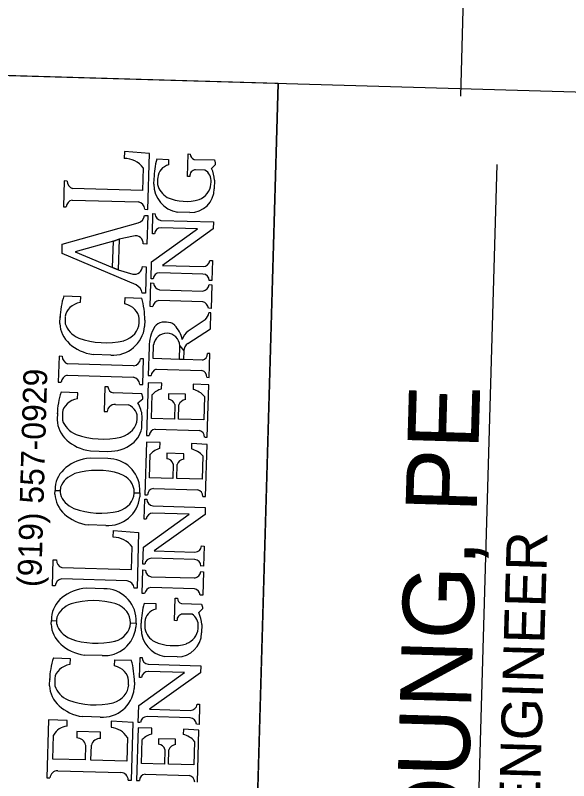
# Model space of a CAD drawing. Extents: x 2097846 to 2099709, y 989477 to 992073.
# Drawn here: x 2099288 to 2099390, y 991266.3 to 991407.2 of the extents above; entities that cross this region are included whole.
import ezdxf

# ---------------------------------------------------------------- set-up
doc = ezdxf.new("R2010")
doc.units = 0
for name, color, linetype in [('Exist Horizontal Alignment Tick Label', 7, 'Continuous'), ('Sheet Block Title CELL', 7, 'Continuous'), ('Sheet Data Field CELL', 7, 'Continuous'), ('Sheet Title CELL', 7, 'Continuous')]:
    doc.layers.add(name, color=color, linetype=linetype)

msp = doc.modelspace()

# ---------------------------------------------------------------- linework, layer by layer
at = {"layer": 'Sheet Block Title CELL'}
for p, q in [((2099308.13, 991382.15), (2099308.09, 991380.9)), ((2099312.76, 991381.78), (2099308.13, 991382.15)), ((2099312.46, 991371.51), (2099312.76, 991381.78)), ((2099319.73, 991377.59), (2099319.85, 991381.72)), ((2099319.85, 991381.72), (2099320.28, 991381.7)), ((2099314.09, 991380.79), (2099316.28, 991380.72)), ((2099316.28, 991380.72), (2099316.25, 991379.69)), ((2099321.01, 991380.72), (2099324.71, 991380.62)), ((2099324.85, 991379.74), (2099324.2, 991379.06)), ((2099324.71, 991380.62), (2099324.86, 991380.06)), ((2099324.86, 991380.06), (2099324.85, 991379.74)), ((2099311.58, 991379.13), (2099311.46, 991374.96)), ((2099322.95, 991378.75), (2099321.25, 991378.8)), ((2099313.55, 991376.13), (2099313.58, 991377.15)), ((2099320.16, 991377.57), (2099319.73, 991377.59)), ((2099324.75, 991376.89), (2099324.7, 991375.32)), ((2099297.01, 991376.74), (2099296.87, 991371.96)), ((2099297.59, 991376.72), (2099297.01, 991376.74)), ((2099324.07, 991376.14), (2099324.1, 991376.53)), ((2099311.46, 991374.96), (2099298.58, 991375.33)), ((2099298.52, 991373.23), (2099310.66, 991372.88)), ((2099296.87, 991371.96), (2099297.4, 991371.95)), ((2099311.91, 991371.53), (2099312.46, 991371.51)), ((2099311.85, 991370.4), (2099312.43, 991370.38)), ((2099312.43, 991370.38), (2099312.28, 991365.12)), ((2099313.28, 991367.02), (2099313.39, 991370.74)), ((2099313.39, 991370.74), (2099313.76, 991370.72)), ((2099320.2, 991370.93), (2099317.89, 991370.99)), ((2099296.68, 991365.13), (2099310.66, 991369.01)), ((2099314.87, 991369.48), (2099324.55, 991369.2)), ((2099324.55, 991369.2), (2099324.51, 991367.91)), ((2099313.14, 991361.87), (2099321.59, 991367.92)), ((2099313.66, 991367.01), (2099313.28, 991367.02)), ((2099321.59, 991367.92), (2099314.89, 991368.12)), ((2099324.51, 991367.91), (2099315.13, 991361.19)), ((2099306.09, 991365.67), (2099299.06, 991363.72)), ((2099305.94, 991360.79), (2099306.09, 991365.67)), ((2099307.14, 991366.01), (2099306.09, 991365.67)), ((2099306.09, 991365.67), (2099307.14, 991366.01)), ((2099307.14, 991366.01), (2099306.98, 991360.39)), ((2099309.81, 991366.56), (2099307.14, 991366.01)), ((2099296.63, 991363.41), (2099296.68, 991365.13)), ((2099312.28, 991365.12), (2099311.56, 991365.14)), ((2099310.27, 991357.6), (2099296.63, 991363.41)), ((2099299.06, 991363.72), (2099305.94, 991360.79)), ((2099313.05, 991358.73), (2099313.14, 991361.87)), ((2099323.86, 991362.1), (2099324.34, 991362.09)), ((2099324.34, 991362.09), (2099324.24, 991358.4)), ((2099305.94, 991360.79), (2099306.98, 991360.39)), ((2099306.98, 991360.39), (2099305.94, 991360.79)), ((2099306.98, 991360.39), (2099309.66, 991359.59)), ((2099311.47, 991360.97), (2099312.16, 991360.95)), ((2099312.16, 991360.95), (2099312.02, 991356.07)), ((2099315.13, 991361.19), (2099322.63, 991360.98)), ((2099313.42, 991358.72), (2099313.05, 991358.73)), ((2099322.59, 991359.6), (2099314.65, 991359.83)), ((2099312.9, 991353.61), (2099313.02, 991357.96)), ((2099313.02, 991357.96), (2099313.5, 991357.95)), ((2099323.74, 991357.65), (2099324.22, 991357.64)), ((2099324.24, 991358.4), (2099323.76, 991358.41)), ((2099324.22, 991357.64), (2099324.09, 991353.29)), ((2099312.02, 991356.07), (2099311.4, 991356.09)), ((2099314.58, 991356.71), (2099322.59, 991356.48)), ((2099296.96, 991355.59), (2099300.03, 991355.5)), ((2099300.03, 991355.5), (2099299.99, 991354.37)), ((2099308.22, 991354.13), (2099308.25, 991355.26)), ((2099308.25, 991355.26), (2099311.31, 991355.17)), ((2099322.56, 991354.51), (2099314.5, 991354.74)), ((2099313.38, 991353.59), (2099312.9, 991353.61)), ((2099324.09, 991353.29), (2099323.61, 991353.3)), ((2099296.24, 991350.47), (2099296.28, 991351.81)), ((2099324.07, 991352.48), (2099323.66, 991352.49)), ((2099323.98, 991349.53), (2099324.07, 991352.48)), ((2099310.82, 991350.64), (2099310.83, 991351.43)), ((2099311.88, 991351.13), (2099311.84, 991349.94)), ((2099322.99, 991351.19), (2099319.9, 991349.06)), ((2099319.82, 991346.82), (2099323.98, 991349.53)), ((2099312.68, 991346.2), (2099312.53, 991340.92)), ((2099313.44, 991344.03), (2099313.51, 991346.55)), ((2099318.26, 991343.89), (2099318.33, 991346.41)), ((2099318.33, 991346.41), (2099319.05, 991345.45)), ((2099318.33, 991346.41), (2099319.05, 991345.45)), ((2099296.08, 991344.47), (2099295.94, 991339.69)), ((2099296.66, 991344.45), (2099296.08, 991344.47)), ((2099305.6, 991344.69), (2099302.36, 991344.78)), ((2099319.05, 991345.45), (2099319, 991343.87)), ((2099323.85, 991344.95), (2099323.44, 991344.96)), ((2099323.72, 991340.58), (2099323.85, 991344.95)), ((2099309.79, 991342.71), (2099297.65, 991343.06)), ((2099311.67, 991343.97), (2099311.12, 991343.99)), ((2099311.53, 991339.24), (2099311.67, 991343.97)), ((2099318.26, 991343.89), (2099313.44, 991344.03)), ((2099319, 991343.87), (2099318.26, 991343.89)), ((2099319, 991343.87), (2099318.26, 991343.89)), ((2099322.53, 991343.77), (2099319, 991343.87)), ((2099313.96, 991342.09), (2099322.42, 991341.85)), ((2099297.59, 991340.96), (2099309.73, 991340.61)), ((2099312.53, 991340.92), (2099313.03, 991340.91)), ((2099323.32, 991340.59), (2099323.72, 991340.58)), ((2099295.94, 991339.69), (2099296.47, 991339.68)), ((2099304.5, 991338.82), (2099304.37, 991334.28)), ((2099305.11, 991338.81), (2099304.5, 991338.82)), ((2099310.98, 991339.26), (2099311.53, 991339.24)), ((2099312.49, 991339.58), (2099312.21, 991329.88)), ((2099315.02, 991339.51), (2099312.49, 991339.58)), ((2099314.99, 991338.44), (2099315.02, 991339.51)), ((2099320.82, 991339.35), (2099320.79, 991338.34)), ((2099323.68, 991339.18), (2099320.82, 991339.35)), ((2099323.41, 991329.56), (2099323.68, 991339.18)), ((2099299.51, 991337.76), (2099296.45, 991337.85)), ((2099299.48, 991336.63), (2099299.51, 991337.76)), ((2099311.31, 991337.57), (2099306.14, 991337.72)), ((2099311.53, 991336.96), (2099311.31, 991337.57)), ((2099313.09, 991333.03), (2099313.22, 991337.4)), ((2099316.26, 991337.57), (2099316.23, 991336.56)), ((2099319.4, 991337.48), (2099316.26, 991337.57)), ((2099319.37, 991336.48), (2099319.4, 991337.48)), ((2099310.61, 991335.87), (2099311.52, 991336.61)), ((2099311.52, 991336.61), (2099311.53, 991336.96)), ((2099322.87, 991337.08), (2099322.75, 991332.75)), ((2099306.49, 991335.61), (2099308.87, 991335.54)), ((2099317.42, 991335.57), (2099317.35, 991332.91)), ((2099318.1, 991332.89), (2099318.17, 991335.5)), ((2099295.77, 991334.07), (2099295.73, 991332.74)), ((2099304.37, 991334.28), (2099304.98, 991334.27)), ((2099311.35, 991331.6), (2099311.4, 991333.47)), ((2099317.35, 991332.91), (2099313.09, 991333.03)), ((2099322.75, 991332.75), (2099318.1, 991332.89)), ((2099313.79, 991331.04), (2099321.96, 991330.81)), ((2099312.21, 991329.88), (2099312.71, 991329.87)), ((2099322.92, 991329.58), (2099323.41, 991329.56)), ((2099312.18, 991328.63), (2099311.9, 991318.94)), ((2099314.71, 991328.56), (2099312.18, 991328.63)), ((2099314.68, 991327.49), (2099314.71, 991328.56)), ((2099320.51, 991328.41), (2099320.48, 991327.4)), ((2099323.37, 991328.23), (2099320.51, 991328.41)), ((2099323.09, 991318.62), (2099323.37, 991328.23)), ((2099301.85, 991327.05), (2099305.08, 991326.95)), ((2099312.78, 991322.09), (2099312.9, 991326.46)), ((2099315.95, 991326.62), (2099315.92, 991325.61)), ((2099319.09, 991326.53), (2099315.95, 991326.62)), ((2099319.06, 991325.53), (2099319.09, 991326.53)), ((2099322.56, 991326.13), (2099322.43, 991321.81)), ((2099305.05, 991325.62), (2099301.81, 991325.71)), ((2099317.11, 991324.63), (2099317.03, 991321.96)), ((2099317.78, 991321.94), (2099317.86, 991324.55)), ((2099317.03, 991321.96), (2099312.78, 991322.09)), ((2099322.43, 991321.81), (2099317.78, 991321.94)), ((2099295.33, 991319.1), (2099295.35, 991319.74)), ((2099295.37, 991320.39), (2099295.35, 991319.74)), ((2099295.35, 991319.74), (2099296.3, 991319.72)), ((2099295.35, 991319.74), (2099296.3, 991319.72)), ((2099309.92, 991319.35), (2099310.96, 991319.29)), ((2099309.92, 991319.35), (2099310.96, 991319.29)), ((2099309.92, 991319.27), (2099309.92, 991319.32)), ((2099310.96, 991319.29), (2099310.94, 991318.57)), ((2099310.96, 991319.29), (2099310.98, 991320.02)), ((2099313.48, 991320.1), (2099321.64, 991319.86)), ((2099311.77, 991314.46), (2099311.88, 991318.18)), ((2099311.88, 991318.18), (2099312.25, 991318.17)), ((2099311.9, 991318.94), (2099312.39, 991318.93)), ((2099322.6, 991318.63), (2099323.09, 991318.62)), ((2099313.36, 991316.92), (2099323.03, 991316.65)), ((2099323.03, 991316.65), (2099323, 991315.35)), ((2099311.62, 991309.31), (2099320.07, 991315.37)), ((2099320.07, 991315.37), (2099313.37, 991315.56)), ((2099323, 991315.35), (2099313.62, 991308.63)), ((2099304.69, 991313.31), (2099301.46, 991313.41)), ((2099312.14, 991314.45), (2099311.77, 991314.46)), ((2099306.08, 991311.14), (2099306.12, 991312.39)), ((2099306.12, 991312.39), (2099310.75, 991312.02)), ((2099310.75, 991312.02), (2099310.45, 991301.75)), ((2099309.45, 991305.2), (2099309.57, 991309.37)), ((2099311.53, 991306.17), (2099311.62, 991309.31)), ((2099322.35, 991309.54), (2099322.83, 991309.53)), ((2099322.83, 991309.53), (2099322.72, 991305.84)), ((2099313.62, 991308.63), (2099321.11, 991308.42)), ((2099294.86, 991302.2), (2099295, 991306.98)), ((2099295, 991306.98), (2099295.58, 991306.96)), ((2099321.08, 991307.04), (2099313.13, 991307.27)), ((2099296.57, 991305.57), (2099309.45, 991305.2)), ((2099311.38, 991300.77), (2099311.5, 991305.12)), ((2099311.5, 991305.12), (2099311.98, 991305.11)), ((2099311.9, 991306.16), (2099311.53, 991306.17)), ((2099322.72, 991305.84), (2099322.24, 991305.85)), ((2099313.06, 991303.87), (2099321.06, 991303.64)), ((2099322.21, 991304.82), (2099322.69, 991304.8)), ((2099322.69, 991304.8), (2099322.57, 991300.45)), ((2099295.39, 991302.19), (2099294.86, 991302.2)), ((2099308.65, 991303.12), (2099296.51, 991303.47)), ((2099304.36, 991301.66), (2099301.12, 991301.76)), ((2099310.45, 991301.75), (2099309.9, 991301.77)), ((2099311.85, 991300.76), (2099311.38, 991300.77)), ((2099321.03, 991301.67), (2099312.98, 991301.9)), ((2099317.37, 991295.79), (2099317.49, 991299.92)), ((2099317.49, 991299.92), (2099317.92, 991299.9)), ((2099322.57, 991300.45), (2099322.09, 991300.46)), ((2099311.74, 991298.99), (2099313.92, 991298.92)), ((2099313.92, 991298.92), (2099313.89, 991297.89)), ((2099318.66, 991298.92), (2099322.35, 991298.82)), ((2099322.5, 991297.94), (2099321.84, 991297.26)), ((2099322.35, 991298.82), (2099322.51, 991298.26)), ((2099322.51, 991298.26), (2099322.5, 991297.94)), ((2099320.6, 991296.95), (2099318.9, 991297)), ((2099294.64, 991295.14), (2099294.66, 991295.79)), ((2099294.68, 991296.43), (2099294.66, 991295.79)), ((2099294.66, 991295.79), (2099295.61, 991295.76)), ((2099294.66, 991295.79), (2099295.61, 991295.76)), ((2099309.23, 991295.39), (2099310.27, 991295.34)), ((2099309.23, 991295.39), (2099310.27, 991295.34)), ((2099309.23, 991295.31), (2099309.23, 991295.37)), ((2099310.27, 991295.34), (2099310.25, 991294.61)), ((2099310.27, 991295.34), (2099310.29, 991296.06)), ((2099311.19, 991294.33), (2099311.22, 991295.35)), ((2099317.81, 991295.77), (2099317.37, 991295.79)), ((2099322.39, 991295.09), (2099322.35, 991293.52)), ((2099321.71, 991294.34), (2099321.74, 991294.73)), ((2099304, 991289.36), (2099300.77, 991289.45)), ((2099295.04, 991288.92), (2099298.1, 991288.83)), ((2099298.1, 991288.83), (2099298.07, 991287.7)), ((2099306.29, 991287.46), (2099306.33, 991288.59)), ((2099306.33, 991288.59), (2099309.39, 991288.51)), ((2099310.93, 991285.31), (2099311.04, 991289.02)), ((2099311.04, 991289.02), (2099311.41, 991289.01)), ((2099317.84, 991289.13), (2099315.53, 991289.2)), ((2099312.52, 991287.77), (2099322.19, 991287.49)), ((2099322.19, 991287.49), (2099322.16, 991286.2)), ((2099310.78, 991280.16), (2099319.23, 991286.21)), ((2099311.3, 991285.3), (2099310.93, 991285.31)), ((2099319.23, 991286.21), (2099312.53, 991286.41)), ((2099322.16, 991286.2), (2099312.78, 991279.48)), ((2099294.32, 991283.81), (2099294.36, 991285.14)), ((2099294.36, 991285.14), (2099294.35, 991284.93)), ((2099308.9, 991283.98), (2099308.91, 991284.76)), ((2099309.96, 991284.46), (2099309.92, 991283.28)), ((2099310.69, 991277.02), (2099310.78, 991280.16)), ((2099321.51, 991280.39), (2099321.99, 991280.38)), ((2099321.99, 991280.38), (2099321.88, 991276.69)), ((2099312.78, 991279.48), (2099320.27, 991279.27)), ((2099294.15, 991277.5), (2099293.84, 991266.85)), ((2099297.59, 991277.4), (2099294.15, 991277.5)), ((2099297.56, 991276.34), (2099297.59, 991277.4)), ((2099303.67, 991278.02), (2099300.44, 991278.12)), ((2099305.7, 991277.3), (2099305.67, 991276.15)), ((2099309.73, 991277.05), (2099305.7, 991277.3)), ((2099309.42, 991266.4), (2099309.73, 991277.05)), ((2099311.06, 991277.01), (2099310.69, 991277.02)), ((2099320.24, 991277.89), (2099312.29, 991278.12)), ((2099299.37, 991275.36), (2099299.33, 991274.2)), ((2099303.74, 991275.24), (2099299.37, 991275.36)), ((2099310.66, 991276.06), (2099310.38, 991266.36)), ((2099313.19, 991275.98), (2099310.66, 991276.06)), ((2099313.16, 991274.91), (2099313.19, 991275.98)), ((2099318.99, 991275.83), (2099318.96, 991274.82)), ((2099321.85, 991275.65), (2099318.99, 991275.83)), ((2099321.88, 991276.69), (2099321.4, 991276.7)), ((2099321.58, 991266.04), (2099321.85, 991275.65)), ((2099294.94, 991270.3), (2099295.06, 991274.73)), ((2099303.71, 991274.07), (2099303.74, 991275.24)), ((2099308.69, 991274.3), (2099308.56, 991269.91)), ((2099314.43, 991274.04), (2099314.4, 991273.03)), ((2099317.57, 991273.95), (2099314.43, 991274.04)), ((2099317.54, 991272.95), (2099317.57, 991273.95)), ((2099300.95, 991272.89), (2099300.88, 991270.13)), ((2099301.95, 991270.1), (2099302.03, 991272.86)), ((2099311.26, 991269.51), (2099311.39, 991273.88)), ((2099321.04, 991273.55), (2099320.92, 991269.23)), ((2099315.59, 991272.05), (2099315.52, 991269.39)), ((2099316.27, 991269.36), (2099316.34, 991271.97)), ((2099300.88, 991270.13), (2099294.94, 991270.3)), ((2099308.56, 991269.91), (2099301.95, 991270.1)), ((2099315.52, 991269.39), (2099311.26, 991269.51)), ((2099320.92, 991269.23), (2099316.27, 991269.36)), ((2099295.85, 991268.14), (2099307.47, 991267.8)), ((2099311.96, 991267.52), (2099320.13, 991267.29)), ((2099293.84, 991266.85), (2099294.41, 991266.83)), ((2099308.83, 991266.42), (2099309.42, 991266.4)), ((2099310.38, 991266.36), (2099310.88, 991266.35))]:
    msp.add_line(p, q, dxfattribs=at)
for centre, radius, start, end in [((2099321.26, 991381.67), 0.984, 178.266, 255.1967), ((2099308.11, 991376.61), 4.29, 36.0398, 90.2805), ((2099329.04, 991376.8), 15.47, 165.0886, 178.7168), ((2099316.88, 991377.14), 2.63, 103.8306, 175.1756), ((2099321.31, 991377.65), 1.15, 93.1, 183.7021), ((2099321.77, 991376.73), 2.34, 354.9193, 59.5785), ((2099318.57, 991376.48), 6.19, 3.7719, 24.6514), ((2099324.52, 991376.68), 10.28, 176.1979, 183.1726), ((2099299.05, 991376.71), 1.46, 179.4703, 251.277), ((2099318.81, 991376.18), 5.27, 180.4982, 259.9255), ((2099317.79, 991376.88), 3.62, 192.2527, 240.6897), ((2099320.78, 991376.44), 3.3, 290.4672, 354.7818), ((2099320.25, 991375.38), 4.45, 269.3014, 359.1909), ((2099298.78, 991371.88), 1.38, 100.6585, 177.0918), ((2099310.46, 991371.44), 1.45, 3.4101, 82.0781), ((2099319.48, 991381.37), 8.39, 245.6303, 286.97), ((2099310.02, 991370.75), 1.86, 290.1973, 349.0445), ((2099314.99, 991370.71), 1.23, 179.1002, 264.2953), ((2099314.85, 991366.92), 1.2, 88.2675, 175.7646), ((2099310.25, 991365.32), 1.32, 352.2555, 109.868), ((2099322.66, 991362.18), 1.2, 268.2675, 356.3141), ((2099309.97, 991361.07), 1.5, 258.1274, 356.364), ((2099314.61, 991358.63), 1.2, 88.2675, 175.7646), ((2099322.56, 991358.4), 1.2, 0.385, 88.4317), ((2099309.37, 991355.74), 2.06, 9.7648, 64.2593), ((2099314.87, 991358.05), 1.37, 184.1151, 257.7956), ((2099322.37, 991357.83), 1.37, 278.9035, 352.584), ((2099298.24, 991351.28), 13.64, 359.3402, 16.5666), ((2099314.74, 991353.39), 1.38, 99.9659, 171.2437), ((2099322.24, 991353.17), 1.38, 5.4554, 76.7333), ((2099321.95, 991352.55), 1.71, 307.3904, 357.9934), ((2099315.27, 991348.86), 1.87, 96.4898, 147.7823), ((2099315.64, 991347.09), 3.67, 73.9325, 99.0294), ((2099316.14, 991348.96), 1.74, 43.8951, 72.7546), ((2099313.64, 991346.48), 5.26, 11.6582, 44.5423), ((2099306, 991350.55), 5.88, 266.0729, 354.0782), ((2099319.74, 991346.23), 7.05, 148.9956, 180.2337), ((2099315.91, 991346.29), 2.42, 2.7737, 173.9255), ((2099321.52, 991346.73), 2.84, 124.8008, 163.4688), ((2099320.74, 991345.4), 1.69, 123.0539, 178.3496), ((2099298.12, 991344.44), 1.46, 179.4703, 251.277), ((2099322.25, 991344.93), 1.2, 283.6308, 1.5329), ((2099309.67, 991344.16), 1.45, 274.5557, 353.289), ((2099314.54, 991340.68), 1.53, 112.3389, 171.392), ((2099322.12, 991340.69), 1.2, 355.1663, 75.6065), ((2099297.85, 991339.61), 1.38, 100.6585, 177.0918), ((2099309.53, 991339.17), 1.45, 3.4101, 82.0781), ((2099316.09, 991334.51), 4.07, 105.6665, 134.8722), ((2099319.89, 991334.51), 3.94, 40.7109, 76.7766), ((2099316.15, 991335.24), 1.32, 14.6251, 86.2099), ((2099319.54, 991335.05), 1.44, 96.6205, 161.8676), ((2099313.92, 991329.84), 1.21, 95.875, 178.5651), ((2099321.62, 991329.56), 1.29, 0.7147, 75.1162), ((2099315.78, 991323.57), 4.07, 105.6665, 134.8722), ((2099319.58, 991323.56), 3.94, 40.7109, 76.7766), ((2099305.11, 991319.75), 5.88, 2.6209, 90.6262), ((2099315.83, 991324.29), 1.32, 14.6251, 86.2099), ((2099319.22, 991324.1), 1.44, 96.6205, 161.8676), ((2099313.6, 991318.9), 1.21, 95.875, 178.5651), ((2099321.31, 991318.62), 1.29, 0.7147, 75.1162), ((2099305.09, 991319.18), 5.88, 266.0729, 354.0782), ((2099313.48, 991318.15), 1.23, 179.1002, 264.2953), ((2099313.34, 991314.36), 1.2, 88.2675, 175.7646), ((2099306.1, 991306.85), 4.29, 36.0398, 90.2805), ((2099321.15, 991309.62), 1.2, 268.2675, 356.3141), ((2099297.04, 991306.95), 1.46, 179.4703, 251.277), ((2099313.1, 991306.07), 1.2, 88.2675, 175.7646), ((2099321.04, 991305.84), 1.2, 0.385, 88.4317), ((2099313.35, 991305.21), 1.37, 184.1151, 257.7956), ((2099320.85, 991304.99), 1.37, 278.9035, 352.584), ((2099296.77, 991302.12), 1.38, 100.6585, 177.0918), ((2099308.45, 991301.68), 1.45, 3.4101, 82.0781), ((2099304.42, 991295.79), 5.88, 2.6209, 90.6262), ((2099313.22, 991300.55), 1.38, 99.9659, 171.2437), ((2099320.72, 991300.33), 1.38, 5.4554, 76.7333), ((2099318.91, 991299.87), 0.984, 178.266, 255.1967), ((2099326.69, 991295), 15.47, 165.0886, 178.7168), ((2099314.52, 991295.34), 2.63, 103.8306, 175.1756), ((2099318.96, 991295.85), 1.15, 93.1, 183.7021), ((2099319.41, 991294.94), 2.34, 354.9193, 59.5785), ((2099316.22, 991294.68), 6.19, 3.7719, 24.6514), ((2099322.16, 991294.88), 10.28, 176.1979, 183.1726), ((2099304.4, 991295.22), 5.88, 266.0729, 354.0782), ((2099316.46, 991294.38), 5.27, 180.4982, 259.9255), ((2099315.43, 991295.08), 3.62, 192.2527, 240.6897), ((2099318.42, 991294.64), 3.3, 290.4672, 354.7818), ((2099317.9, 991293.58), 4.45, 269.3014, 359.1909), ((2099317.13, 991299.57), 8.39, 245.6303, 286.97), ((2099296.32, 991284.62), 13.64, 359.3402, 16.5666), ((2099312.64, 991288.99), 1.23, 179.1002, 264.2953), ((2099312.5, 991285.21), 1.2, 88.2675, 175.7646), ((2099304.08, 991283.88), 5.88, 266.0729, 354.0782), ((2099320.31, 991280.47), 1.2, 268.2675, 356.3141), ((2099312.26, 991276.92), 1.2, 88.2675, 175.7646), ((2099320.2, 991276.69), 1.2, 0.385, 88.4317), ((2099297.8, 991273.23), 3.12, 94.458, 151.3146), ((2099305.23, 991272.03), 4.13, 33.2462, 83.8894), ((2099299.34, 991272.54), 1.66, 12.3011, 90.0648), ((2099303.63, 991272.42), 1.66, 87.1289, 164.398), ((2099314.26, 991270.99), 4.07, 105.6665, 134.8722), ((2099318.06, 991270.99), 3.94, 40.7109, 76.7766), ((2099314.32, 991271.72), 1.32, 14.6251, 86.2099), ((2099317.71, 991271.53), 1.44, 96.6205, 161.8676), ((2099295.82, 991266.72), 1.42, 88.7118, 175.5232), ((2099307.42, 991266.39), 1.42, 1.176, 87.9873), ((2099312.09, 991266.32), 1.21, 95.875, 178.5651), ((2099319.79, 991266.04), 1.29, 0.7147, 75.1162)]:
    msp.add_arc(centre, radius, start, end, dxfattribs=at)
for centre, major_axis, ratio, start_param, end_param in [((2099317.93, 991351.08), (-21.65, 0.62), 0.785714, 6.051738, 6.289595), ((2099300.89, 991351.55), (-3.68, 0.11), 0.785714, 4.982585, 6.22779), ((2099307.15, 991351.37), (-3.68, 0.11), 0.785714, 3.196988, 4.442193), ((2099311.59, 991350.98), (-14.39, 0.41), 0.785714, 6.245633, 6.367364), ((2099303.61, 991350.48), (-7.37, 0.21), 0.785714, 0.0375, 1.423769), ((2099302.17, 991351.26), (-5.06, 0.15), 0.785714, 0.242655, 1.08804), ((2099306.36, 991350.75), (-4.47, 0.13), 0.812926, 1.956822, 3.148618), ((2099304.5, 991356.18), (-11.74, 0.34), 0.785714, 1.17427, 1.895784), ((2099306.48, 991338.77), (-1.38, 0.04), 0.785714, 6.281728, 7.624421), ((2099317.41, 991333.34), (-21.65, 0.62), 0.785714, 6.051738, 6.289595), ((2099300.38, 991333.82), (-3.68, 0.11), 0.785714, 4.982585, 6.22779), ((2099306.59, 991334.34), (-1.62, 0.05), 0.785714, 4.7953, 6.376605), ((2099307.23, 991333.33), (-3.27, 0.09), 0.785714, 3.012278, 4.210239), ((2099302.76, 991333.07), (-8.66, 0.25), 0.785714, 3.23623, 3.600647), ((2099311.08, 991333.25), (-14.39, 0.41), 0.785714, 6.245633, 6.367364), ((2099303.1, 991332.74), (-7.37, 0.21), 0.785714, 0.0375, 1.423769), ((2099301.66, 991333.52), (-5.06, 0.15), 0.785714, 0.242655, 1.08804), ((2099305.12, 991331.85), (-6.23, 0.18), 0.785714, 1.587409, 3.156276), ((2099305.85, 991333.01), (-4.62, 0.13), 0.785714, 1.956822, 3.148618), ((2099303.99, 991338.45), (-11.74, 0.34), 0.785714, 1.17427, 1.895784), ((2099302.73, 991319.96), (7.37, -0.21), 0.785714, 1.717824, 3.104092), ((2099303.29, 991314.21), (11.74, -0.34), 0.785714, 1.245809, 1.967323), ((2099301.25, 991319.26), (5.06, -0.15), 0.785714, 2.053552, 2.898937), ((2099305.46, 991319.53), (4.47, -0.13), 0.812926, 6.27616, 7.467956), ((2099302.7, 991319.1), (-7.37, 0.21), 0.785714, 0.0375, 1.423769), ((2099310.67, 991318.99), (14.39, -0.41), 0.785714, 3.057414, 3.114429), ((2099310.69, 991319.61), (-14.39, 0.41), 0.785714, 0.027164, 0.084179), ((2099301.27, 991319.88), (-5.06, 0.15), 0.785714, 0.242655, 1.08804), ((2099305.45, 991319.37), (-4.47, 0.13), 0.812926, 1.956822, 3.148618), ((2099303.6, 991324.81), (-11.74, 0.34), 0.785714, 1.17427, 1.895784), ((2099302.04, 991296), (7.37, -0.21), 0.785714, 1.717824, 3.104092), ((2099302.6, 991290.25), (11.74, -0.34), 0.785714, 1.245809, 1.967323), ((2099300.56, 991295.3), (5.06, -0.15), 0.785714, 2.053552, 2.898937), ((2099304.77, 991295.57), (4.47, -0.13), 0.812926, 6.27616, 7.467956), ((2099302.01, 991295.15), (-7.37, 0.21), 0.785714, 0.0375, 1.423769), ((2099309.98, 991295.04), (14.39, -0.41), 0.785714, 3.057414, 3.114429), ((2099310, 991295.65), (-14.39, 0.41), 0.785714, 0.027164, 0.084179), ((2099300.58, 991295.93), (-5.06, 0.15), 0.785714, 0.242655, 1.08804), ((2099304.76, 991295.41), (-4.47, 0.13), 0.812926, 1.956822, 3.148618), ((2099302.91, 991300.85), (-11.74, 0.34), 0.785714, 1.17427, 1.895784), ((2099316, 991284.41), (-21.65, 0.62), 0.785714, 6.051738, 6.289595), ((2099298.97, 991284.89), (-3.68, 0.11), 0.785714, 4.982585, 6.22779), ((2099305.23, 991284.71), (-3.68, 0.11), 0.785714, 3.196988, 4.442193), ((2099301.69, 991283.81), (-7.37, 0.21), 0.785714, 0.0375, 1.423769), ((2099309.67, 991284.32), (-14.39, 0.41), 0.785714, 6.245633, 6.367364), ((2099304.44, 991284.08), (-4.47, 0.13), 0.812926, 1.956822, 3.148618), ((2099300.25, 991284.59), (-5.06, 0.15), 0.785714, 0.242655, 1.08804), ((2099302.58, 991289.52), (-11.74, 0.34), 0.785714, 1.17427, 1.895784)]:
    msp.add_ellipse(centre, major_axis=major_axis, ratio=ratio, start_param=start_param, end_param=end_param, dxfattribs=at)
at = {"layer": 'Sheet Title CELL'}
for p, q in [((2099370.11, 991392.37), (2099379.64, 991723.24)), ((2099490.15, 991390.27), (2099250.25, 991397.18)), ((2099336.46, 991394.69), (2099328.96, 991134.63)), ((2099370.1, 991147.17), (2099376.85, 991379.8))]:
    msp.add_line(p, q, dxfattribs=at)
msp.add_lwpolyline([(2099323.27, 990937.38), (2099336.45, 991394.69), (2099258.59, 991396.94), (2099245.41, 990939.63)], close=True, dxfattribs=at)

# ---------------------------------------------------------------- texts
at = {"layer": 'Exist Horizontal Alignment Tick Label'}
msp.add_text('(919) 557-0929', height=4.3957, rotation=88.3496, dxfattribs=at).set_placement((2099292.78, 991301.93))
at = {"layer": 'Sheet Data Field CELL'}
msp.add_text('ANDY YOUNG, PE', height=13.1252, rotation=88.3433, dxfattribs=at).set_placement((2099369.35, 991187.82))
at = {"layer": 'Sheet Title CELL'}
msp.add_text('PROJECT ENGINEER', height=7.4993, rotation=88.3433, dxfattribs=at).set_placement((2099383.18, 991210.16))

doc.saveas('drawing.dxf')
